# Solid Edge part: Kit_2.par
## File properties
Sűrűség: 0,000 kg/m^3
Pontosság: 0,990
Author: ahadarics
Last saved by: ahadarics
Revision: 76
Username: ahadarics
Dokumentum tartalom típus: 0
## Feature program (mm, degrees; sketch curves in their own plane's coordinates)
base feature "unnamed BaseFeature 1"
sketch for "Furat_1" plane through (0, 0, 4.5) normal (0, 0, 1) x-axis (-1, 0, 0)
  hole centre (0, 0) bore radius 2.067
hole "Furat_1" nominal diameter 5 finite  ThreadDepth = 4.5 mm
chamfer "Letörés_1" setback 0.5
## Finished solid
Body 1: solid body, 16 faces, 16 edges, 0 vertices.
  Faces by surface: cylinder 7, plane 5, cone 4
  Edges by curve: circle 16
Bounding box of the edges (mm): 19.000 x 19.000 x 16.000, from (-9.5, -9.5, -11.5) to (9.5, 9.5, 4.5).
Cylindrical faces by radius (mm): R0.55 x1, R2.06 x1, R2.067 x1, R7.25 x1, R8 x1, R8.6 x1, R9.5 x1
Conical faces (half-angle, radius in mm at the cone's reference point): 30 deg R7.9134 x1, 45 deg R2.567 x1, 45 deg R7.625 x1, 59 deg R1.0335 x1
Planar faces by outward normal: +z 2, -z 3
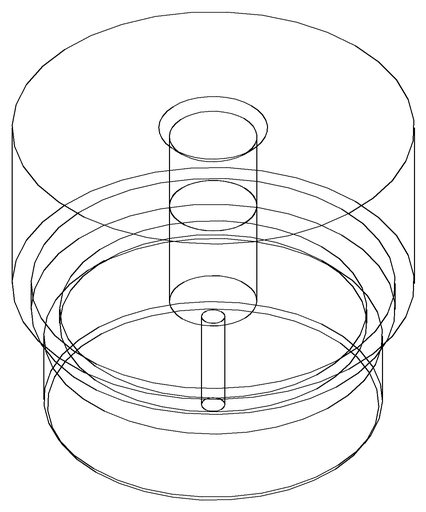
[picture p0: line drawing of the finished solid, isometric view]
